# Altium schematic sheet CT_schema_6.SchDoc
size 287 x 160 mm
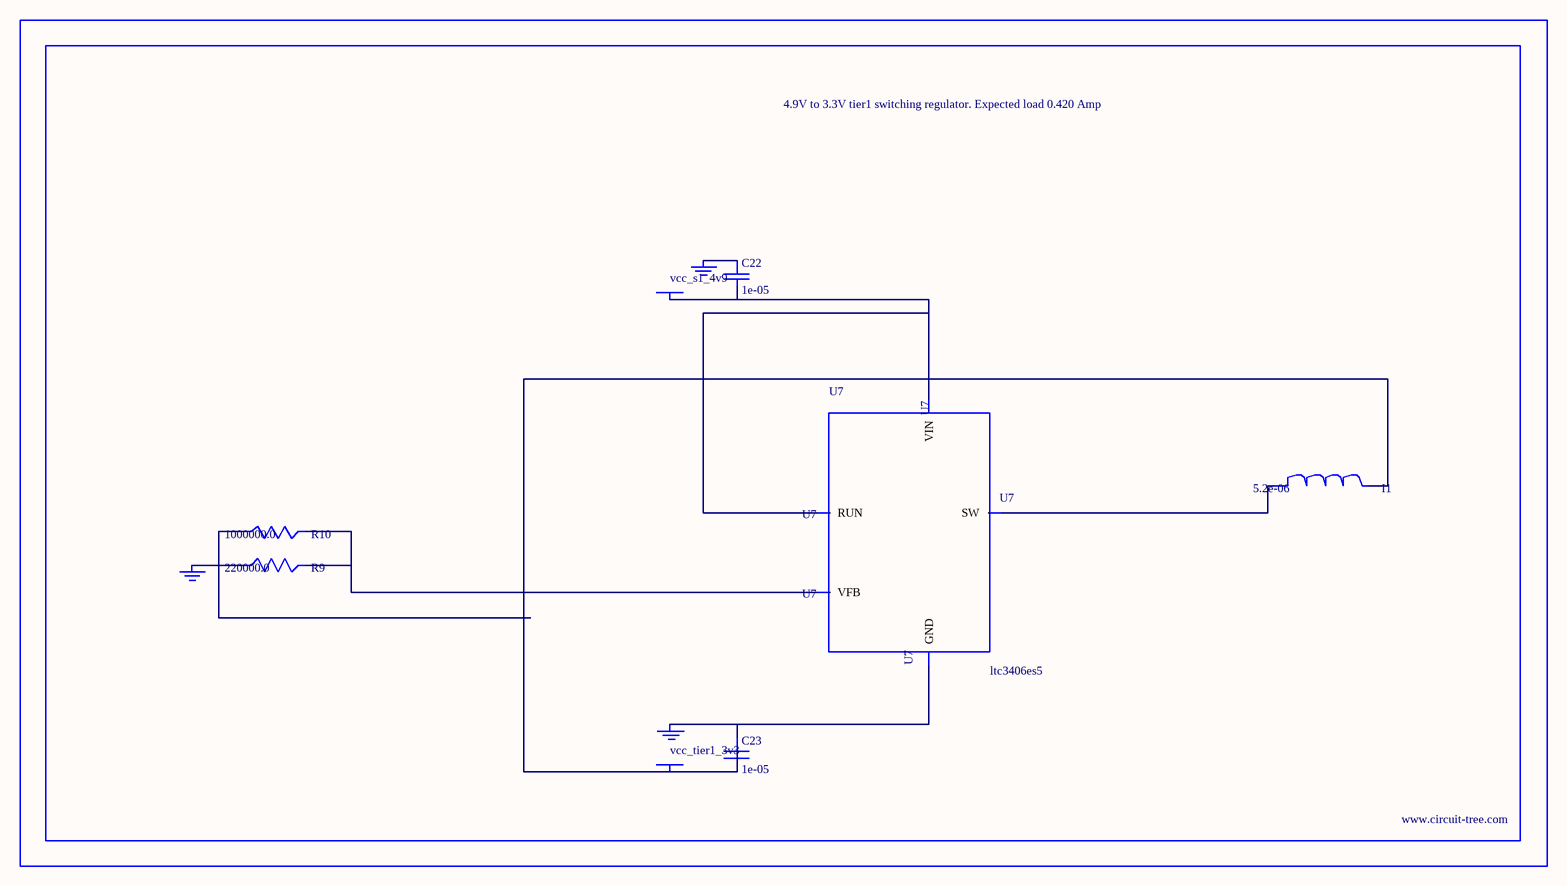
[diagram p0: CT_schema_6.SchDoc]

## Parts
BORDER5  (no value)
C22  1e-05  [C0805]
C23  1e-05  [C0805]
GND_INSTANCE_5_0  (no value)
GND_INSTANCE_5_1  (no value)
GND_INSTANCE_5_2  (no value)
I1  5.2e-06  [DR1040]
POWER_INSTANCE_5_0  vcc_tier1_3v3
POWER_INSTANCE_5_1  vcc_s1_4v9
R9  220000.0  [R0603]
R10  1000000.0  [R0603]
U7  ltc3406es5  [TSOT-23-5]

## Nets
NetC22_1: C22.1 GND_INSTANCE_5_1.0(GND)
NetC22_2: C22.2 POWER_INSTANCE_5_1.0(PWR) U7.1(RUN) U7.4(VIN)
NetC23_1: C23.1 GND_INSTANCE_5_0.0(GND) U7.2(GND)
NetC23_2: C23.2 I1.2 POWER_INSTANCE_5_0.0(PWR) R10.1
NetGND_INSTANCE_5_2_0: GND_INSTANCE_5_2.0(GND) R9.1
NetI1_1: I1.1 U7.3(SW)
NetR9_2: R9.2 R10.2 U7.5(VFB)

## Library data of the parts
BORDER5 = BORDER_PAGE5
C22 C23 = C0805C106K8RACTU
GND_INSTANCE_5_0-GND_INSTANCE_5_2 = GND
I1 = DR1040-5R2-R
POWER_INSTANCE_5_0 POWER_INSTANCE_5_1 = PWR
R9 = RC0603JR-07220KL
R10 = RC0603JR-071ML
